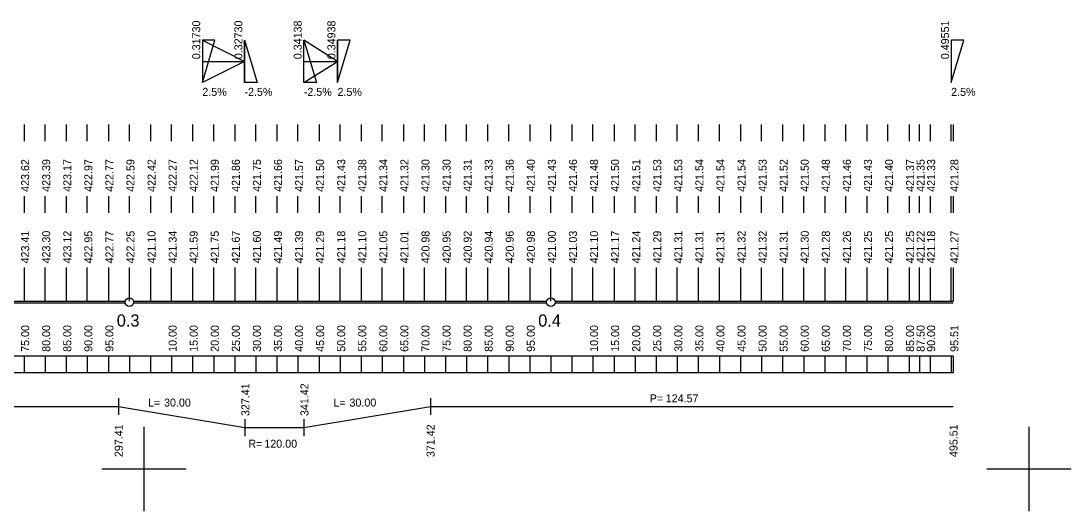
# Model space of a CAD drawing. Extents: x -122 to 738, y -15 to 302.
# Drawn here: x 279.3 to 528.4, y -14.8 to 101.6 of the extents above; entities that cross this region are included whole.
import ezdxf

# ---------------------------------------------------------------- set-up
doc = ezdxf.new("R2010")
doc.units = 0
for name, color, linetype in [('1', 7, 'Continuous'), ('2', 7, 'Continuous'), ('FORMATY', 7, 'Continuous')]:
    doc.layers.add(name, color=color, linetype=linetype)

msp = doc.modelspace()

# ---------------------------------------------------------------- linework, layer by layer
at = {"layer": '1'}
for p, q in [((280, 77), (280, 73)), ((285, 73), (285, 77)), ((290, 77), (290, 73)), ((295, 73), (295, 77)), ((300, 77), (300, 73)), ((305, 73), (305, 77)), ((310, 77), (310, 73)), ((315, 73), (315, 77)), ((320, 77), (320, 73)), ((325, 73), (325, 77)), ((330, 77), (330, 73)), ((335, 73), (335, 77)), ((340, 77), (340, 73)), ((345, 73), (345, 77)), ((350, 77), (350, 73)), ((355, 73), (355, 77)), ((360, 77), (360, 73)), ((365, 73), (365, 77)), ((370, 77), (370, 73)), ((375, 73), (375, 77)), ((380, 77), (380, 73)), ((385, 73), (385, 77)), ((390, 77), (390, 73)), ((395, 73), (395, 77)), ((400, 77), (400, 73)), ((405, 73), (405, 77)), ((410, 77), (410, 73)), ((415, 73), (415, 77)), ((420, 77), (420, 73)), ((425, 73), (425, 77)), ((430, 77), (430, 73)), ((435, 73), (435, 77)), ((440, 77), (440, 73)), ((445, 73), (445, 77)), ((450, 77), (450, 73)), ((455, 73), (455, 77)), ((460, 77), (460, 73)), ((465, 73), (465, 77)), ((470, 77), (470, 73)), ((475, 73), (475, 77)), ((480, 77), (480, 73)), ((485, 73), (485, 77)), ((490, 77), (490, 73)), ((492.5, 73), (492.5, 77)), ((495, 77), (495, 73)), ((500, 73), (500, 77)), ((500.51, 77), (500.51, 73)), ((280, 60), (280, 56)), ((285, 56), (285, 60)), ((290, 60), (290, 56)), ((295, 56), (295, 60)), ((300, 60), (300, 56)), ((305, 56), (305, 60)), ((310, 60), (310, 56)), ((315, 56), (315, 60)), ((320, 60), (320, 56)), ((325, 56), (325, 60)), ((330, 60), (330, 56)), ((335, 56), (335, 60)), ((340, 60), (340, 56)), ((345, 56), (345, 60)), ((350, 60), (350, 56)), ((355, 56), (355, 60)), ((360, 60), (360, 56)), ((365, 56), (365, 60)), ((370, 60), (370, 56)), ((375, 56), (375, 60)), ((380, 60), (380, 56)), ((385, 56), (385, 60)), ((390, 60), (390, 56)), ((395, 56), (395, 60)), ((400, 60), (400, 56)), ((405, 56), (405, 60)), ((410, 60), (410, 56)), ((415, 56), (415, 60)), ((420, 60), (420, 56)), ((425, 56), (425, 60)), ((430, 60), (430, 56)), ((435, 56), (435, 60)), ((440, 60), (440, 56)), ((445, 56), (445, 60)), ((450, 60), (450, 56)), ((455, 56), (455, 60)), ((460, 60), (460, 56)), ((465, 56), (465, 60)), ((470, 60), (470, 56)), ((475, 56), (475, 60)), ((480, 60), (480, 56)), ((485, 56), (485, 60)), ((490, 60), (490, 56)), ((492.5, 56), (492.5, 60)), ((495, 60), (495, 56)), ((500, 56), (500, 60)), ((500.51, 60), (500.51, 56)), ((280, 43), (280, 35)), ((285, 35), (285, 43)), ((290, 43), (290, 35)), ((295, 35), (295, 43)), ((300, 43), (300, 35)), ((305, 35), (305, 43)), ((310, 43), (310, 35)), ((315, 35), (315, 43)), ((320, 43), (320, 35)), ((325, 35), (325, 43)), ((330, 43), (330, 35)), ((335, 35), (335, 43)), ((340, 43), (340, 35)), ((345, 35), (345, 43)), ((350, 43), (350, 35)), ((355, 35), (355, 43)), ((360, 43), (360, 35)), ((365, 35), (365, 43)), ((370, 43), (370, 35)), ((375, 35), (375, 43)), ((380, 43), (380, 35)), ((385, 35), (385, 43)), ((390, 43), (390, 35)), ((395, 35), (395, 43)), ((400, 43), (400, 35)), ((405, 35), (405, 43)), ((410, 43), (410, 35)), ((415, 35), (415, 43)), ((420, 43), (420, 35)), ((425, 35), (425, 43)), ((430, 43), (430, 35)), ((435, 35), (435, 43)), ((440, 43), (440, 35)), ((445, 35), (445, 43)), ((450, 43), (450, 35)), ((455, 35), (455, 43)), ((460, 43), (460, 35)), ((465, 35), (465, 43)), ((470, 43), (470, 35)), ((475, 35), (475, 43)), ((480, 43), (480, 35)), ((485, 35), (485, 43)), ((490, 43), (490, 35)), ((492.5, 35), (492.5, 43)), ((495, 43), (495, 35)), ((500, 35), (500, 43)), ((500.51, 43), (500.51, 35)), ((206, 35), (304, 35)), ((306, 35), (404, 35)), ((406, 35), (500.51, 35)), ((206, 34.6), (304, 34.6)), ((306, 34.6), (404, 34.6)), ((406, 34.6), (500.51, 34.6)), ((500.51, 22), (5, 22)), ((280, 22), (280, 18)), ((285, 22), (285, 18)), ((290, 22), (290, 18)), ((295, 22), (295, 18)), ((300, 22), (300, 18)), ((305, 22), (305, 18)), ((310, 22), (310, 18)), ((315, 22), (315, 18)), ((320, 22), (320, 18)), ((325, 22), (325, 18)), ((330, 22), (330, 18)), ((335, 22), (335, 18)), ((340, 22), (340, 18)), ((345, 22), (345, 18)), ((350, 22), (350, 18)), ((355, 22), (355, 18)), ((360, 22), (360, 18)), ((365, 22), (365, 18)), ((370, 22), (370, 18)), ((375, 22), (375, 18)), ((380, 22), (380, 18)), ((385, 22), (385, 18)), ((390, 22), (390, 18)), ((395, 22), (395, 18)), ((400, 22), (400, 18)), ((405, 22), (405, 18)), ((410, 22), (410, 18)), ((415, 22), (415, 18)), ((420, 22), (420, 18)), ((425, 22), (425, 18)), ((430, 22), (430, 18)), ((435, 22), (435, 18)), ((440, 22), (440, 18)), ((445, 22), (445, 18)), ((450, 22), (450, 18)), ((455, 22), (455, 18)), ((460, 22), (460, 18)), ((465, 22), (465, 18)), ((470, 22), (470, 18)), ((475, 22), (475, 18)), ((480, 22), (480, 18)), ((485, 22), (485, 18)), ((490, 22), (490, 18)), ((492.5, 22), (492.5, 18)), ((495, 22), (495, 18)), ((500, 22), (500, 18)), ((500.51, 22), (500.51, 18)), ((500.51, 18), (5, 18))]:
    msp.add_line(p, q, dxfattribs=at)
for centre in [(305, 34.8), (405, 34.8)]:
    msp.add_circle(centre, 1, dxfattribs=at)
at = {"layer": '2'}
for p, q in [((322.3, 97), (322.3, 87)), ((322.3, 87), (325.3, 97)), ((325.3, 97), (322.3, 97)), ((322.3, 97), (332.3, 92)), ((332.3, 87), (332.3, 97)), ((332.3, 97), (335.3, 87)), ((332.3, 97), (332.3, 92)), ((346.38, 87), (346.38, 97)), ((346.38, 97), (349.38, 87)), ((354.38, 92), (346.38, 97)), ((354.38, 97), (354.38, 87)), ((354.38, 87), (357.38, 97)), ((357.38, 97), (354.38, 97)), ((354.38, 92), (354.38, 97)), ((500, 97), (500, 87)), ((500, 87), (503, 97)), ((503, 97), (500, 97)), ((500, 97), (500, 87)), ((500, 87), (503, 97)), ((503, 97), (500, 97)), ((500, 97), (500, 97)), ((500, 97), (500, 97)), ((322.3, 92), (332.3, 92)), ((332.3, 92), (322.3, 87)), ((332.3, 92), (332.3, 87)), ((346.38, 92), (354.38, 92)), ((346.38, 87), (354.38, 92)), ((354.38, 87), (354.38, 92)), ((500, 92), (500, 92)), ((335.3, 87), (332.3, 87)), ((349.38, 87), (346.38, 87)), ((500, 87), (500, 87)), ((500, 87), (500, 87)), ((186.89, 10), (302.41, 10)), ((302.41, 12), (302.41, 8)), ((302.41, 10), (332.41, 5)), ((346.42, 5), (376.42, 10)), ((376.42, 12), (376.42, 8)), ((376.42, 10), (500.51, 10)), ((332.41, 7), (332.41, 3)), ((332.41, 5), (346.42, 5)), ((346.42, 7), (346.42, 3))]:
    msp.add_line(p, q, dxfattribs=at)
at = {"layer": 'FORMATY'}
for p, q in [((308.44, 5.19), (308.44, -14.81)), ((308.44, 5.19), (308.44, -14.81)), ((308.44, 5.19), (308.44, -14.81)), ((518.44, 5.19), (518.44, -14.81)), ((518.44, 5.19), (518.44, -14.81)), ((518.44, 5.19), (518.44, -14.81)), ((298.44, -4.81), (318.44, -4.81)), ((298.44, -4.81), (318.44, -4.81)), ((298.44, -4.81), (318.44, -4.81)), ((508.44, -4.81), (528.44, -4.81)), ((508.44, -4.81), (528.44, -4.81)), ((508.44, -4.81), (528.44, -4.81))]:
    msp.add_line(p, q, dxfattribs=at)

# ---------------------------------------------------------------- texts
at = {"layer": '1'}
for s, p in [('423.41', (281.2, 44)), ('423.30', (286.2, 44)), ('423.12', (291.2, 44)), ('422.95', (296.2, 44)), ('422.77', (301.2, 44)), ('422.25', (306.2, 44)), ('421.10', (311.2, 44)), ('421.34', (316.2, 44)), ('421.59', (321.2, 44)), ('421.75', (326.2, 44)), ('421.67', (331.2, 44)), ('421.60', (336.2, 44)), ('421.49', (341.2, 44)), ('421.39', (346.2, 44)), ('421.29', (351.2, 44)), ('421.18', (356.2, 44)), ('421.10', (361.2, 44)), ('421.05', (366.2, 44)), ('421.01', (371.2, 44)), ('420.98', (376.2, 44)), ('420.95', (381.2, 44)), ('420.92', (386.2, 44)), ('420.94', (391.2, 44)), ('420.96', (396.2, 44)), ('420.98', (401.2, 44)), ('421.00', (406.2, 44)), ('421.03', (411.2, 44)), ('421.10', (416.2, 44)), ('421.17', (421.2, 44)), ('421.24', (426.2, 44)), ('421.29', (431.2, 44)), ('421.31', (436.2, 44)), ('421.31', (441.2, 44)), ('421.31', (446.2, 44)), ('421.32', (451.2, 44)), ('421.32', (456.2, 44)), ('421.31', (461.2, 44)), ('421.30', (466.2, 44)), ('421.28', (471.2, 44)), ('421.26', (476.2, 44)), ('421.25', (481.2, 44)), ('421.25', (486.2, 44)), ('421.25', (491.2, 44)), ('421.22', (493.7, 44)), ('421.18', (496.2, 44)), ('421.27', (501.71, 44)), ('75.00', (281.2, 23)), ('80.00', (286.2, 23)), ('85.00', (291.2, 23)), ('90.00', (296.2, 23)), ('95.00', (301.2, 23)), ('10.00', (316.2, 23)), ('15.00', (321.2, 23)), ('20.00', (326.2, 23)), ('25.00', (331.2, 23)), ('30.00', (336.2, 23)), ('35.00', (341.2, 23)), ('40.00', (346.2, 23)), ('45.00', (351.2, 23)), ('50.00', (356.2, 23)), ('55.00', (361.2, 23)), ('60.00', (366.2, 23)), ('65.00', (371.2, 23)), ('70.00', (376.2, 23)), ('75.00', (381.2, 23)), ('80.00', (386.2, 23)), ('85.00', (391.2, 23)), ('90.00', (396.2, 23)), ('95.00', (401.2, 23)), ('10.00', (416.2, 23)), ('15.00', (421.2, 23)), ('20.00', (426.2, 23)), ('25.00', (431.2, 23)), ('30.00', (436.2, 23)), ('35.00', (441.2, 23)), ('40.00', (446.2, 23)), ('45.00', (451.2, 23)), ('50.00', (456.2, 23)), ('55.00', (461.2, 23)), ('60.00', (466.2, 23)), ('65.00', (471.2, 23)), ('70.00', (476.2, 23)), ('75.00', (481.2, 23)), ('80.00', (486.2, 23)), ('85.00', (491.2, 23)), ('87.50', (493.7, 23)), ('90.00', (496.2, 23)), ('95.51', (501.71, 23))]:
    msp.add_text(s, height=1.9, rotation=90, dxfattribs=at).set_placement(p)
for s, p in [('0.3', (302, 29)), ('0.4', (402, 29))]:
    msp.add_text(s, height=2.9, dxfattribs=at).set_placement(p)
at = {"layer": '2'}
for s, p in [('0.31730', (321.8, 92.5)), ('0.32730', (331.8, 92.5)), ('0.32730', (331.8, 92.5)), ('0.34138', (345.88, 92.5)), ('0.34938', (353.88, 92.5)), ('0.34938', (353.88, 92.5)), ('0.49551', (499.5, 92.5)), ('423.62', (281.2, 61)), ('423.39', (286.2, 61)), ('423.17', (291.2, 61)), ('422.97', (296.2, 61)), ('422.77', (301.2, 61)), ('422.59', (306.2, 61)), ('422.42', (311.2, 61)), ('422.27', (316.2, 61)), ('422.12', (321.2, 61)), ('421.99', (326.2, 61)), ('421.86', (331.2, 61)), ('421.75', (336.2, 61)), ('421.66', (341.2, 61)), ('421.57', (346.2, 61)), ('421.50', (351.2, 61)), ('421.43', (356.2, 61)), ('421.38', (361.2, 61)), ('421.34', (366.2, 61)), ('421.32', (371.2, 61)), ('421.30', (376.2, 61)), ('421.30', (381.2, 61)), ('421.31', (386.2, 61)), ('421.33', (391.2, 61)), ('421.36', (396.2, 61)), ('421.40', (401.2, 61)), ('421.43', (406.2, 61)), ('421.46', (411.2, 61)), ('421.48', (416.2, 61)), ('421.50', (421.2, 61)), ('421.51', (426.2, 61)), ('421.53', (431.2, 61)), ('421.53', (436.2, 61)), ('421.54', (441.2, 61)), ('421.54', (446.2, 61)), ('421.54', (451.2, 61)), ('421.53', (456.2, 61)), ('421.52', (461.2, 61)), ('421.50', (466.2, 61)), ('421.48', (471.2, 61)), ('421.46', (476.2, 61)), ('421.43', (481.2, 61)), ('421.40', (486.2, 61)), ('421.37', (491.2, 61)), ('421.35', (493.7, 61)), ('421.33', (496.2, 61)), ('421.28', (501.71, 61)), ('327.41', (333.47, 7.74)), ('341.42', (347.48, 7.74)), ('297.41', (303.41, -2)), ('371.42', (377.42, -2)), ('495.51', (501.51, -2))]:
    msp.add_text(s, height=1.9, rotation=90, dxfattribs=at).set_placement(p)
for s, p in [('2.5%', (322.3, 83.8)), ('-2.5%', (332.3, 83.8)), ('-2.5%', (346.38, 83.8)), ('2.5%', (354.38, 83.8)), ('2.5%', (500, 83.8)), ('2.5%', (500, 83.8)), ('P=', (428.46, 11)), ('124.57', (432.26, 11)), ('L=', (309.41, 10)), ('30.00', (313.21, 10)), ('L=', (353.42, 10)), ('30.00', (357.22, 10)), ('R=', (333.22, 0.23)), ('120.00', (337.02, 0.23))]:
    msp.add_text(s, height=1.9, dxfattribs=at).set_placement(p)

doc.saveas('drawing.dxf')
